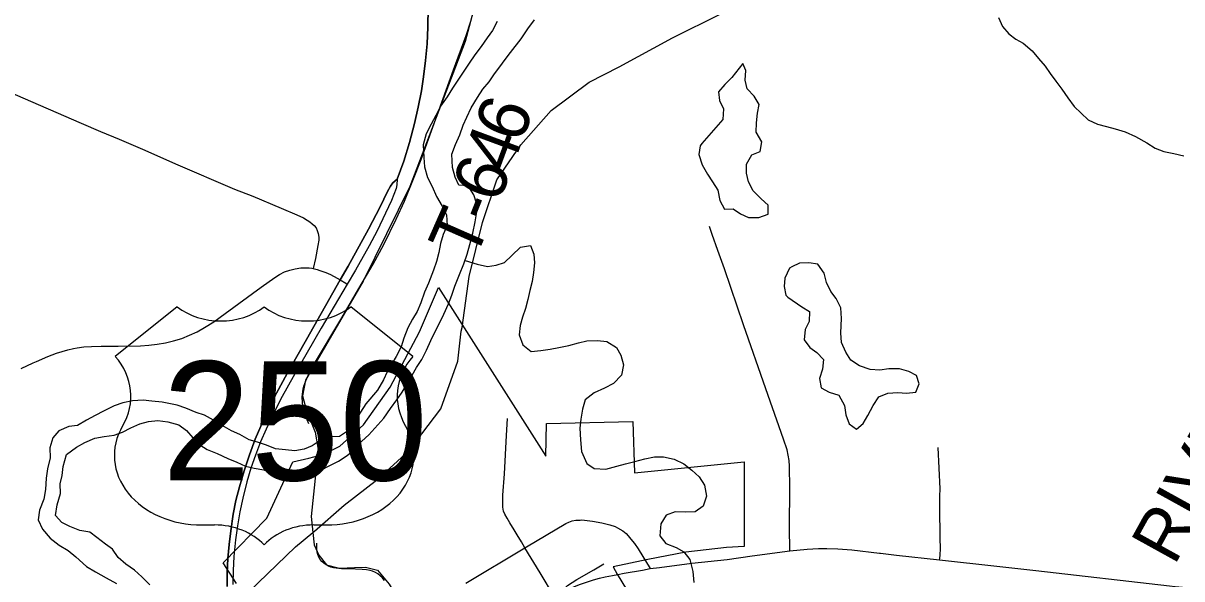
# Model space of a CAD drawing. Extents: x 0 to 34, y 0 to 22.
# Drawn here: x 24.267 to 25.55, y 16.248 to 16.863 of the extents above; entities that cross this region are included whole.
import ezdxf

# ---------------------------------------------------------------- set-up
doc = ezdxf.new("R2010")
doc.units = 0
for name, color, linetype in [('GM_X_City_Street', 7, 'Continuous'), ('GM_X_Corporation', 7, 'Continuous'), ('GM_X_Major_River', 7, 'Continuous'), ('GM_X_Minor_Lake', 7, 'Continuous'), ('GM_X_Minor_River', 7, 'Continuous'), ('GM_X_Rail_Line', 7, 'Continuous'), ('GM_X_State_Route', 7, 'Continuous'), ('GM_X_Township_Road', 7, 'Continuous'), ('GM_X_Township_Road_Text', 7, 'Continuous'), ('GM_X_US_Location', 7, 'Continuous'), ('GM_X_US_Route', 7, 'Continuous'), ('GM_X_US_Shield', 7, 'Continuous')]:
    doc.layers.add(name, color=color, linetype=linetype)

msp = doc.modelspace()

# ---------------------------------------------------------------- linework, layer by layer
at = {"layer": 'GM_X_City_Street'}
for points in [[(24.8556, 16.2277), (24.8398, 16.2543), (24.8228, 16.2821), (24.8189, 16.2885), (24.814, 16.2964), (24.8107, 16.3018), (24.806, 16.3096), (24.8032, 16.3148), (24.8005, 16.3191), (24.7991, 16.3226), (24.7981, 16.3269), (24.7981, 16.3335), (24.7984, 16.3401), (24.8001, 16.364), (24.8024, 16.4062), (24.8036, 16.4253)], [(24.7573, 16.2428), (24.8228, 16.2821), (24.8244, 16.2832), (24.868, 16.3089), (24.8715, 16.3105), (24.8749, 16.3117), (24.8791, 16.3127), (24.8838, 16.3127), (24.8856, 16.3128)], [(24.8856, 16.3128), (24.8974, 16.3116), (24.9079, 16.3096), (24.9168, 16.3075), (24.9226, 16.3054), (24.9253, 16.3041), (24.931, 16.3009), (24.935, 16.2978), (24.9369, 16.2954), (24.9402, 16.2917), (24.9441, 16.2867), (24.9481, 16.281), (24.9613, 16.259)], [(24.6671, 16.2457), (24.6647, 16.249), (24.6624, 16.2511), (24.6598, 16.2533), (24.6571, 16.2547), (24.6541, 16.2561), (24.6512, 16.2568), (24.6474, 16.2575), (24.6425, 16.258), (24.6351, 16.2583), (24.6197, 16.2588), (24.6137, 16.2593), (24.6107, 16.2598), (24.6079, 16.2606), (24.6051, 16.2618), (24.6025, 16.2632), (24.6001, 16.265), (24.5979, 16.2669), (24.596, 16.2691), (24.5945, 16.2717), (24.5934, 16.2744), (24.5925, 16.2772), (24.5923, 16.2809), (24.5922, 16.2871)], [(24.8603, 16.2312), (24.87, 16.2401), (24.8804, 16.247), (24.899, 16.2577), (24.9102, 16.2644)]]:
    msp.add_lwpolyline(points, dxfattribs=at)
at = {"layer": 'GM_X_Corporation'}
msp.add_lwpolyline([(24.5034, 16.2426), (24.4887, 16.2654), (24.537, 16.3147), (24.5656, 16.3773), (24.5834, 16.3814), (24.6001, 16.3856), (24.6179, 16.3946), (24.6441, 16.4181), (24.6734, 16.4598), (24.7058, 16.5213), (24.7271, 16.5702), (24.846, 16.3835), (24.8465, 16.4196), (24.9423, 16.4217), (24.9441, 16.3651), (25.0657, 16.3773), (25.0655, 16.2836), (25.0461, 16.2824), (25.0011, 16.2771), (24.9589, 16.2692), (24.9206, 16.261), (24.9249, 16.2529), (24.9454, 16.2188)], dxfattribs=at)
at = {"layer": 'GM_X_Major_River'}
for points in [[(24.3661, 16.2806), (24.3581, 16.2859), (24.3485, 16.2934), (24.3409, 16.2994), (24.3299, 16.3013), (24.3188, 16.3054), (24.31, 16.3099), (24.3028, 16.3178), (24.3046, 16.3296), (24.3083, 16.3422), (24.3079, 16.3528), (24.3104, 16.362), (24.3115, 16.3722), (24.3152, 16.3852), (24.3262, 16.3936), (24.3353, 16.3986), (24.3463, 16.4033), (24.3569, 16.4052), (24.3679, 16.4068), (24.377, 16.4099), (24.3864, 16.4149), (24.3963, 16.4192), (24.4058, 16.4219), (24.416, 16.4231), (24.4274, 16.4216), (24.4396, 16.4183), (24.448, 16.4119), (24.4549, 16.4039), (24.4626, 16.396), (24.4709, 16.3907), (24.482, 16.3863), (24.4938, 16.381), (24.5037, 16.3769), (24.5132, 16.3724), (24.5228, 16.3702), (24.5334, 16.3683), (24.5425, 16.3646), (24.5524, 16.3624), (24.5631, 16.3602), (24.5737, 16.3602), (24.5859, 16.3637), (24.5961, 16.3676), (24.6067, 16.373), (24.6162, 16.378), (24.626, 16.3841), (24.6332, 16.3906), (24.6422, 16.4002), (24.6498, 16.4071), (24.6566, 16.4144), (24.6664, 16.4254), (24.6739, 16.4361), (24.681, 16.4457), (24.6867, 16.4545), (24.6931, 16.4648), (24.6979, 16.4732), (24.7028, 16.4816), (24.7085, 16.4907), (24.7137, 16.501), (24.7186, 16.5117), (24.7238, 16.5224), (24.7283, 16.5308), (24.7328, 16.5407), (24.738, 16.5521), (24.7418, 16.5616), (24.7451, 16.5719), (24.7504, 16.5845), (24.7552, 16.5963), (24.7589, 16.607), (24.7619, 16.6177), (24.7652, 16.6306), (24.7678, 16.6428), (24.7696, 16.6542), (24.7692, 16.6637), (24.7661, 16.6728), (24.7599, 16.6827), (24.7497, 16.6837), (24.7454, 16.6924), (24.7427, 16.7031), (24.7418, 16.7179), (24.7459, 16.7286), (24.7508, 16.7392), (24.7545, 16.7499), (24.7583, 16.7587), (24.7631, 16.7693), (24.7703, 16.7808), (24.7763, 16.79), (24.7831, 16.798), (24.7891, 16.8068), (24.7951, 16.8148), (24.8008, 16.8228), (24.8068, 16.8305), (24.8184, 16.8457), (24.826, 16.8568), (24.8335, 16.8667)], [(24.7921, 16.865), (24.7869, 16.8547), (24.7808, 16.8466), (24.7741, 16.8371), (24.7673, 16.8279), (24.7609, 16.8188), (24.7485, 16.7997), (24.7425, 16.7909), (24.7365, 16.7813), (24.7293, 16.771), (24.7241, 16.7607), (24.7188, 16.7512), (24.7132, 16.7405), (24.7102, 16.7283), (24.7107, 16.7143), (24.7115, 16.704), (24.715, 16.6919), (24.72, 16.682), (24.7247, 16.671), (24.7312, 16.6604), (24.7358, 16.6506), (24.7367, 16.6388), (24.7322, 16.6289), (24.7292, 16.619), (24.7274, 16.6091), (24.7248, 16.5992), (24.7214, 16.5896), (24.7158, 16.5752), (24.7117, 16.5649), (24.7076, 16.5534), (24.7035, 16.5435), (24.6983, 16.5351), (24.693, 16.5256), (24.6885, 16.5142), (24.6856, 16.5046), (24.6803, 16.494), (24.6754, 16.4856), (24.6702, 16.4768), (24.6661, 16.468), (24.6593, 16.4566), (24.6465, 16.4413), (24.6405, 16.4321), (24.6345, 16.4222), (24.6262, 16.4111), (24.6175, 16.4054), (24.605, 16.4049), (24.5959, 16.4007), (24.5872, 16.3949), (24.5781, 16.3914), (24.5678, 16.3895), (24.5576, 16.3905), (24.5465, 16.3916), (24.5366, 16.3957), (24.5264, 16.3991), (24.5172, 16.4017), (24.5069, 16.4073), (24.4978, 16.4114), (24.4875, 16.4175), (24.4779, 16.4235), (24.468, 16.4287), (24.4585, 16.4317), (24.4471, 16.4366), (24.4376, 16.44), (24.4208, 16.4433), (24.4094, 16.4443)], [(24.4094, 16.4443), (24.3999, 16.4454), (24.3881, 16.4446), (24.3775, 16.4426), (24.3677, 16.4391), (24.3559, 16.4334), (24.3468, 16.4284), (24.337, 16.4233), (24.3272, 16.4176), (24.3177, 16.4164), (24.3067, 16.4117), (24.2999, 16.4037), (24.2966, 16.3927), (24.297, 16.3817), (24.2941, 16.3695), (24.2926, 16.3592), (24.2916, 16.3466), (24.2901, 16.336), (24.2853, 16.3238), (24.2838, 16.3131), (24.2884, 16.3025), (24.2969, 16.2927), (24.3068, 16.2848), (24.3167, 16.2791), (24.3255, 16.272), (24.337, 16.2614), (24.3473, 16.2554), (24.3591, 16.2486), (24.3705, 16.2426)], [(24.4074, 16.2409), (24.3986, 16.25), (24.3902, 16.2572), (24.3807, 16.2639), (24.3722, 16.2711), (24.3661, 16.2806)]]:
    msp.add_lwpolyline(points, dxfattribs=at)
at = {"layer": 'GM_X_Minor_Lake'}
for points in [[(25.0187, 16.7298), (25.0168, 16.7272), (25.0154, 16.7174), (25.0192, 16.706), (25.025, 16.6957), (25.0304, 16.6874), (25.0365, 16.678), (25.0385, 16.6666), (25.0439, 16.6571), (25.0534, 16.6575), (25.0614, 16.6519), (25.0702, 16.6478), (25.0819, 16.6478), (25.0922, 16.6513), (25.0921, 16.6616), (25.0845, 16.6684), (25.0757, 16.6774), (25.0703, 16.6873), (25.0683, 16.6968), (25.0682, 16.707), (25.0739, 16.717), (25.0833, 16.7208), (25.0852, 16.7315), (25.079, 16.7421), (25.0793, 16.7527), (25.0804, 16.7634), (25.0822, 16.7729), (25.0765, 16.782), (25.0688, 16.7903), (25.0668, 16.7998), (25.0675, 16.8104), (25.0641, 16.8184)], [(25.0641, 16.8184), (25.052, 16.8027), (25.0441, 16.7951), (25.0373, 16.7871), (25.0381, 16.7772), (25.0427, 16.7681), (25.0421, 16.7563), (25.0187, 16.7298)], [(25.1184, 16.5933), (25.1158, 16.5918), (25.1105, 16.5807), (25.1098, 16.5712), (25.1118, 16.5617), (25.1138, 16.5594)], [(25.1138, 16.5594), (25.1294, 16.5489), (25.1381, 16.5436), (25.1374, 16.5326), (25.1333, 16.5238), (25.1319, 16.5124), (25.1384, 16.5037), (25.146, 16.4981), (25.1533, 16.4905), (25.1522, 16.4799), (25.1489, 16.4696), (25.1509, 16.4593), (25.1596, 16.4544), (25.1703, 16.4511), (25.1768, 16.4397), (25.1781, 16.4291), (25.1819, 16.4192), (25.1899, 16.4132), (25.1975, 16.4197), (25.2024, 16.4285), (25.2084, 16.4395), (25.2148, 16.4491), (25.2246, 16.4533), (25.2356, 16.4538), (25.2455, 16.4531), (25.2558, 16.4543), (25.2595, 16.4634), (25.2564, 16.4729), (25.248, 16.4774), (25.2377, 16.48), (25.2256, 16.4803), (25.2157, 16.4787), (25.2051, 16.4794), (25.1933, 16.4835), (25.1837, 16.4896), (25.178, 16.4987), (25.1733, 16.5093), (25.1725, 16.5199), (25.1735, 16.5359), (25.1727, 16.5477), (25.1673, 16.5579), (25.1615, 16.5658), (25.1569, 16.5757), (25.1542, 16.5863), (25.1473, 16.5962), (25.137, 16.5976), (25.1267, 16.5972), (25.1184, 16.5933)]]:
    msp.add_lwpolyline(points, dxfattribs=at)
at = {"layer": 'GM_X_Minor_River'}
for points in [[(25.3471, 16.8692), (25.3517, 16.8594), (25.3586, 16.8511), (25.3663, 16.8454), (25.3747, 16.8409), (25.3846, 16.8322), (25.3915, 16.8239), (25.3991, 16.8152), (25.4045, 16.8073), (25.4107, 16.7989), (25.4172, 16.7899), (25.4241, 16.7804), (25.431, 16.7706), (25.4467, 16.7558), (25.4569, 16.751), (25.4668, 16.7484), (25.4764, 16.7461), (25.4874, 16.7428), (25.4988, 16.7375), (25.5114, 16.7304), (25.5206, 16.7247), (25.5305, 16.721), (25.5415, 16.7188), (25.5525, 16.7162)], [(24.7566, 16.6003), (24.77, 16.596), (24.7814, 16.5935), (24.7909, 16.595), (24.8, 16.5981), (24.8083, 16.6058), (24.8178, 16.615), (24.8288, 16.6169), (24.8326, 16.6071), (24.8335, 16.5976), (24.8324, 16.5869), (24.8306, 16.577), (24.8283, 16.5671), (24.8261, 16.5569), (24.8232, 16.547), (24.8202, 16.5374), (24.8176, 16.5283), (24.8165, 16.518), (24.8204, 16.5066), (24.8296, 16.4995), (24.8402, 16.5003), (24.8508, 16.5019), (24.8603, 16.5039), (24.8713, 16.5062), (24.8819, 16.5089), (24.8914, 16.5113), (24.9032, 16.5117), (24.9135, 16.5103), (24.9241, 16.5039), (24.9288, 16.4952), (24.9319, 16.4845), (24.9297, 16.4731), (24.921, 16.4639), (24.9108, 16.4589), (24.8994, 16.4535), (24.8896, 16.4459), (24.8866, 16.4356), (24.8848, 16.4246), (24.8837, 16.4143), (24.8842, 16.4014), (24.8854, 16.3888), (24.8912, 16.3755), (24.8996, 16.3699), (24.9125, 16.3692), (24.9247, 16.3723), (24.9342, 16.3751), (24.9444, 16.3774), (24.9554, 16.3805), (24.9664, 16.3829), (24.9763, 16.3826), (24.9881, 16.3803), (24.9987, 16.3751), (25.0075, 16.3679), (25.0159, 16.3604), (25.0217, 16.3513), (25.0237, 16.3391), (25.0203, 16.3281), (25.0113, 16.3219), (25.0002, 16.3215), (24.9892, 16.3218), (24.979, 16.3183), (24.9734, 16.3084), (24.9723, 16.2951), (24.9788, 16.2868), (24.9903, 16.2823), (24.9987, 16.2774), (25.0055, 16.2691), (25.0087, 16.2558), (25.0099, 16.2436)]]:
    msp.add_lwpolyline(points, dxfattribs=at)
at = {"layer": 'GM_X_Rail_Line'}
for points in [[(23.9534, 18.2458), (24.664, 17.1222), (24.7215, 17.0326), (24.7452, 16.9948), (24.7657, 16.9641), (24.7728, 16.9344), (24.7713, 16.8983), (24.7564, 16.8427), (24.6954, 16.6821), (24.6435, 16.5772), (24.5797, 16.4676), (24.5763, 16.4501), (24.5806, 16.4352), (24.5905, 16.41), (24.5938, 16.391), (24.586, 16.3168), (24.588, 16.2989)], [(24.588, 16.2989), (24.5898, 16.3004), (24.6225, 16.3293), (24.6602, 16.3585), (24.6947, 16.3899), (24.7297, 16.4359), (24.7486, 16.4887), (24.7521, 16.522), (24.7532, 16.526), (24.7609, 16.5823), (24.7758, 16.6423), (24.7917, 16.6896), (24.8182, 16.7283), (24.8519, 16.7664), (24.8938, 16.7977), (24.9273, 16.8148), (24.9862, 16.8467), (25.0396, 16.8733)], [(24.3445, 15.3697), (24.3336, 15.4316), (24.3197, 15.4925), (24.2932, 15.5797), (24.2795, 15.6434), (24.2712, 15.6958), (24.2679, 15.756), (24.2749, 15.8089), (24.2835, 15.8528), (24.2951, 15.8979), (24.3105, 15.9423), (24.332, 15.9915), (24.3534, 16.0268), (24.3794, 16.0593), (24.4065, 16.0948), (24.4073, 16.0965), (24.4714, 16.1788), (24.5065, 16.2231), (24.5686, 16.2831), (24.588, 16.2989)], [(24.588, 16.2989), (24.5895, 16.2851), (24.5946, 16.2739), (24.6031, 16.2633), (24.6172, 16.2594), (24.6341, 16.2601), (24.6461, 16.2605), (24.6593, 16.2571), (24.6724, 16.2416), (24.9991, 15.7028), (25.1917, 15.3863), (25.2081, 15.3677)]]:
    msp.add_lwpolyline(points, dxfattribs=at)
at = {"layer": 'GM_X_State_Route'}
for points in [[(24.6812, 16.6901), (24.6886, 16.7102), (24.6949, 16.7309), (24.7004, 16.7519), (24.7046, 16.7699), (24.7081, 16.7881), (24.7105, 16.8034), (24.7127, 16.8217), (24.7143, 16.8402), (24.7153, 16.8587), (24.7157, 16.8803), (24.7153, 16.902), (24.7143, 16.9205), (24.7126, 16.9389), (24.7102, 16.9573), (24.7068, 16.9787), (24.7031, 16.9968), (24.6988, 17.0149), (24.694, 17.0328), (24.6885, 17.0505), (24.6814, 17.0709), (24.6737, 17.0911), (24.6722, 17.0946)], [(24.6182, 16.5786), (24.6268, 16.594), (24.6494, 16.6348), (24.6624, 16.6596), (24.6705, 16.6764), (24.6738, 16.6826), (24.6766, 16.6861), (24.6812, 16.6901)], [(24.2782, 16.4868), (24.2818, 16.4884), (24.2944, 16.4938), (24.3041, 16.4974), (24.3104, 16.4994), (24.3165, 16.5013), (24.3228, 16.5026), (24.3268, 16.5034), (24.3342, 16.5046), (24.3426, 16.5049), (24.3536, 16.5052), (24.3722, 16.5054), (24.397, 16.5057), (24.4063, 16.5063), (24.4155, 16.5074), (24.4246, 16.509), (24.4337, 16.5112), (24.4426, 16.5139), (24.4512, 16.5173), (24.4596, 16.5213), (24.4677, 16.5258), (24.4781, 16.5324), (24.4908, 16.5413), (24.5308, 16.5705), (24.5458, 16.5814), (24.551, 16.5847), (24.5565, 16.5875), (24.5623, 16.5896), (24.5683, 16.5911), (24.5744, 16.592), (24.5806, 16.5922), (24.5837, 16.592), (24.5868, 16.5916), (24.5882, 16.5913), (24.5898, 16.591), (24.5928, 16.5902), (24.5957, 16.5892), (24.6023, 16.5869), (24.6073, 16.5848), (24.6147, 16.5807), (24.6182, 16.5786)], [(24.4929, 16.239), (24.4931, 16.2545), (24.4938, 16.27), (24.4951, 16.2855), (24.4969, 16.3009), (24.4997, 16.3192), (24.5027, 16.3344), (24.5065, 16.3495), (24.5118, 16.3673), (24.5176, 16.385), (24.5241, 16.4024), (24.5301, 16.4168), (24.5378, 16.4337), (24.5476, 16.4531), (24.5595, 16.4749), (24.581, 16.5127), (24.6182, 16.5786)], [(24.6182, 16.5786), (24.6245, 16.575), (24.626, 16.5741)], [(24.2649, 16.4805), (24.2782, 16.4868)], [(24.9257, 16.2525), (24.9326, 16.2539), (24.9528, 16.2573), (24.9613, 16.259), (24.9719, 16.2603), (25.0075, 16.2649), (25.0466, 16.2692), (25.0744, 16.273)], [(25.0744, 16.273), (25.1161, 16.2785), (25.1354, 16.2806), (25.1477, 16.2813), (25.157, 16.2814), (25.1693, 16.2809), (25.1848, 16.2796), (25.2156, 16.2762), (25.2166, 16.2761)], [(25.2166, 16.2761), (25.2341, 16.274), (25.282, 16.2687), (25.3453, 16.2616), (25.3886, 16.2568), (25.5368, 16.2399), (25.5428, 16.2393), (25.5549, 16.238), (25.5863, 16.2346), (25.6115, 16.2319), (25.6172, 16.2313), (25.7655, 16.2146), (25.8767, 16.2025), (25.9355, 16.1963), (25.9681, 16.1929), (26.0128, 16.1881), (26.0809, 16.1815), (26.0964, 16.1804), (26.1089, 16.1802), (26.1245, 16.1806), (26.14, 16.1817), (26.2327, 16.1916), (26.378, 16.2072), (26.4182, 16.2113)], [(24.8486, 16.2235), (24.8556, 16.2277), (24.8603, 16.2312), (24.8769, 16.2389), (24.8831, 16.2412), (24.8919, 16.2444), (24.8986, 16.2464), (24.9054, 16.2482), (24.9116, 16.2497), (24.9196, 16.2513), (24.9257, 16.2525)]]:
    msp.add_lwpolyline(points, dxfattribs=at)
at = {"layer": 'GM_X_Township_Road'}
for points in [[(24.5835, 16.4194), (24.5799, 16.428), (24.578, 16.4338), (24.5773, 16.4368), (24.5765, 16.4429), (24.5762, 16.449), (24.5764, 16.452), (24.5767, 16.455), (24.5773, 16.458), (24.578, 16.461), (24.58, 16.4668), (24.5839, 16.4752), (24.5898, 16.4861), (24.62, 16.5368), (24.6389, 16.5691), (24.6545, 16.596), (24.6664, 16.6179), (24.6802, 16.6458), (24.6892, 16.6657), (24.6987, 16.6887), (24.7077, 16.7119), (24.7437, 16.8113), (24.7575, 16.8492), (24.7624, 16.864)], [(24.1762, 16.8195), (24.3312, 16.7522), (24.3525, 16.7429), (24.3732, 16.7344), (24.4016, 16.7223), (24.4356, 16.7072), (24.5012, 16.6793), (24.5213, 16.6714), (24.5526, 16.6581), (24.5702, 16.6509), (24.5774, 16.6475), (24.5815, 16.6449), (24.5844, 16.6431), (24.5872, 16.6408), (24.5894, 16.6388), (24.5916, 16.6362), (24.5928, 16.6335), (24.5939, 16.6299), (24.5944, 16.6259), (24.5944, 16.6228), (24.5935, 16.6167), (24.5908, 16.6025), (24.5882, 16.5913)], [(25.1161, 16.2785), (25.1158, 16.3047), (25.1163, 16.3479), (25.1158, 16.3723), (25.1153, 16.3785), (25.1144, 16.3846), (25.113, 16.3906), (25.1093, 16.4024), (25.0894, 16.4582), (25.0648, 16.5288), (25.0436, 16.5908), (25.0365, 16.6114), (25.0303, 16.629), (25.0273, 16.6377)], [(25.282, 16.2687), (25.2822, 16.2702), (25.2827, 16.2743), (25.2829, 16.2809), (25.2828, 16.2932), (25.2822, 16.3268), (25.2824, 16.3392), (25.2825, 16.3472), (25.2806, 16.3929)]]:
    msp.add_lwpolyline(points, dxfattribs=at)
at = {"layer": 'GM_X_US_Route'}
for points in [[(24.6722, 17.0946), (24.6737, 17.0911), (24.6814, 17.0709), (24.6885, 17.0505), (24.694, 17.0328), (24.6988, 17.0149), (24.7031, 16.9968), (24.7068, 16.9787), (24.7102, 16.9573), (24.7126, 16.9389), (24.7143, 16.9205), (24.7153, 16.902), (24.7157, 16.8803), (24.7153, 16.8587), (24.7143, 16.8402), (24.7127, 16.8217), (24.7105, 16.8034), (24.7081, 16.7881), (24.7046, 16.7699), (24.7004, 16.7519), (24.6949, 16.7309), (24.6886, 16.7102), (24.6812, 16.6901)], [(24.6812, 16.6901), (24.681, 16.6839), (24.6801, 16.68), (24.6748, 16.6666), (24.6685, 16.6525), (24.659, 16.6329), (24.6503, 16.6165), (24.635, 16.5895), (24.626, 16.5741), (24.5972, 16.5252), (24.566, 16.4715), (24.554, 16.4497), (24.5454, 16.4331), (24.536, 16.4135), (24.5298, 16.3992), (24.5242, 16.3847), (24.5192, 16.37), (24.5148, 16.3551), (24.5102, 16.3369), (24.507, 16.3217), (24.5043, 16.3064), (24.5023, 16.291), (24.5005, 16.2724), (24.4996, 16.2568), (24.4993, 16.2413)], [(24.6812, 16.6901), (24.6766, 16.6861), (24.6738, 16.6826), (24.6705, 16.6764), (24.6624, 16.6596), (24.6494, 16.6348), (24.6268, 16.594), (24.6182, 16.5786)], [(24.6182, 16.5786), (24.581, 16.5127), (24.5595, 16.4749), (24.5476, 16.4531), (24.5378, 16.4337), (24.5301, 16.4168), (24.5241, 16.4024), (24.5176, 16.385), (24.5118, 16.3673), (24.5065, 16.3495), (24.5027, 16.3344), (24.4997, 16.3192), (24.4969, 16.3009), (24.4951, 16.2855), (24.4938, 16.27), (24.4931, 16.2545), (24.4929, 16.239)]]:
    msp.add_lwpolyline(points, dxfattribs=at)
at = {"layer": 'GM_X_US_Shield'}
for p, q in [((24.4377, 16.549), (24.3691, 16.494)), ((24.6987, 16.494), (24.63, 16.549)), ((24.4652, 16.3073), (24.4789, 16.3073)), ((24.5888, 16.3073), (24.6025, 16.3073))]:
    msp.add_line(p, q, dxfattribs=at)
for centre, major_axis, start_param, end_param in [((24.4858, 16.5882), (-0.0687, 0), 0.795399, 2.346194), ((24.5819, 16.5882), (-0.0687, 0), 0.795399, 2.346194), ((24.2903, 16.4499), (0.0961, 0), 5.838949, 6.894067), ((24.7774, 16.4499), (-0.0961, 0), 5.672304, 6.727422), ((24.4641, 16.3842), (0.0961, 0), 2.702327, 4.723529), ((24.6036, 16.3842), (-0.0961, 0), 1.559657, 3.580859), ((24.4789, 16.2523), (-0.0687, 0), 3.785094, 4.712389), ((24.5888, 16.2523), (-0.0687, 0), 4.712389, 5.639684)]:
    msp.add_ellipse(centre, major_axis=major_axis, ratio=0.8, start_param=start_param, end_param=end_param, dxfattribs=at)

# ---------------------------------------------------------------- texts
at = {"layer": 'GM_X_Township_Road_Text'}
for s, height, rotation, p in [('6', 0.0568, 69.8642, (24.8185, 16.7282)), ('4', 0.0568, 69.6792, (24.8063, 16.6952)), ('6', 0.0568, 68.9663, (24.7934, 16.6618)), ('T', 0.0568, 66.2612, (24.7665, 16.5985)), ('-', 0.0568, 68.2025, (24.7845, 16.6394)), ('RIVER', 0.05682, 61.0995, (25.5419, 16.2612))]:
    msp.add_text(s, height=height, rotation=rotation, dxfattribs=at).set_placement(p)
at = {"layer": 'GM_X_US_Location'}
for s in ['0', '/']:
    msp.add_text(s, height=0.000189, dxfattribs=at).set_placement((24.534, 16.4225))
msp.add_text('250', height=0.000189, rotation=0, dxfattribs=at).set_placement((24.4757, 16.3833))
at = {"layer": 'GM_X_US_Shield'}
msp.add_text('250', height=0.13184, dxfattribs=at).set_placement((24.4211, 16.3567))

doc.saveas('drawing.dxf')
